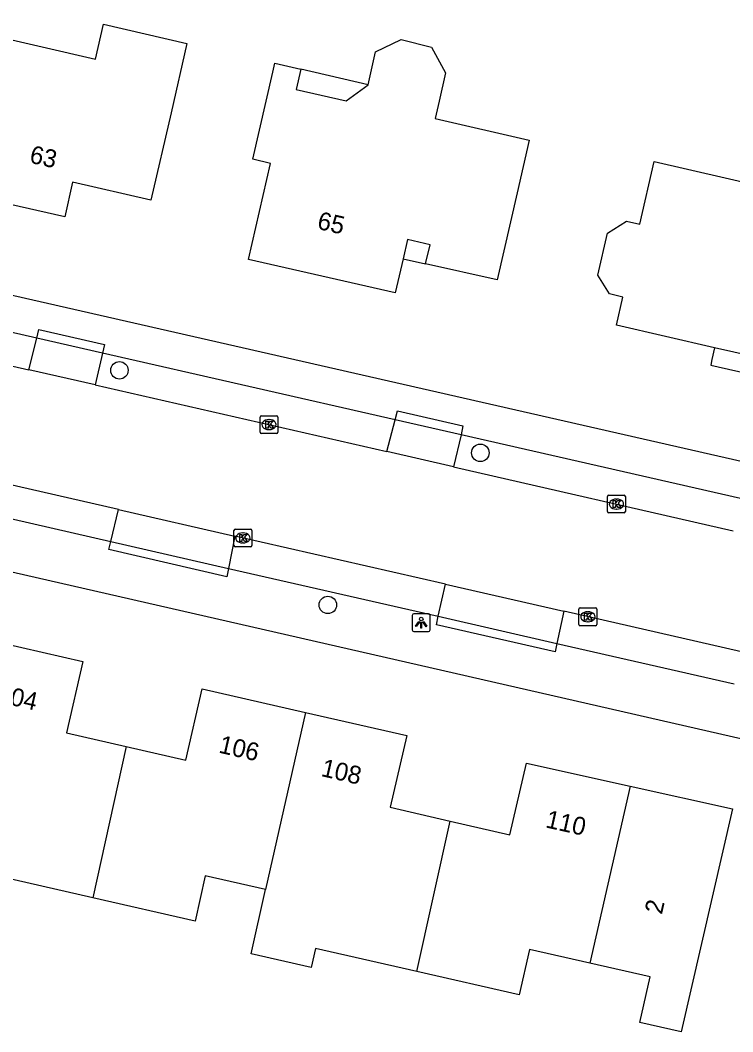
# Model space of a CAD drawing. Extents: x 159628 to 160723, y 388176 to 389416.
# Drawn here: x 160277.9 to 160317.8, y 388682.2 to 388738.8 of the extents above; entities that cross this region are included whole.
import ezdxf

# ---------------------------------------------------------------- set-up
doc = ezdxf.new("R2010")
doc.units = 0
for name, color, linetype in [('IMGEO_Boom', 7, 'Continuous'), ('IMGEO_Kolk', 7, 'Continuous'), ('IMGEO_Lichtpunt', 7, 'Continuous'), ('IMGEO_Pand', 7, 'Continuous'), ('IMGEO_Pand_nummerreeks', 7, 'Continuous'), ('IMGEO_Pand_overbouw', 7, 'Continuous'), ('IMGEO_Parkeervlak_open', 7, 'Continuous'), ('IMGEO_Rijbaan_lokaal_gesloten', 7, 'Continuous'), ('IMGEO_Voetpad_open', 7, 'Continuous')]:
    doc.layers.add(name, color=color, linetype=linetype)

msp = doc.modelspace()

# ---------------------------------------------------------------- linework, layer by layer
at = {"layer": 'IMGEO_Boom'}
for centre in [(160283.483, 388719.176), (160303.688, 388714.56), (160295.153, 388706.051)]:
    msp.add_circle(centre, 0.489, dxfattribs=at)
at = {"layer": 'IMGEO_Kolk'}
for p, q in [((160291.358, 388715.712), (160291.358, 388716.564)), ((160291.433, 388716.638), (160292.285, 388716.638)), ((160291.846, 388716.418), (160291.871, 388716.418)), ((160292.359, 388716.564), (160292.359, 388715.712)), ((160291.869, 388715.858), (160291.844, 388715.858)), ((160292.285, 388715.638), (160291.433, 388715.638)), ((160310.81, 388711.268), (160310.81, 388712.12)), ((160310.885, 388712.194), (160311.737, 388712.194)), ((160311.298, 388711.974), (160311.323, 388711.974)), ((160311.811, 388712.12), (160311.811, 388711.268)), ((160311.321, 388711.414), (160311.296, 388711.414)), ((160311.737, 388711.194), (160310.885, 388711.194)), ((160289.895, 388709.37), (160289.895, 388710.222)), ((160289.97, 388710.296), (160290.822, 388710.296)), ((160290.383, 388710.076), (160290.408, 388710.076)), ((160290.896, 388710.222), (160290.896, 388709.37)), ((160290.406, 388709.516), (160290.381, 388709.516)), ((160290.822, 388709.296), (160289.97, 388709.296)), ((160309.209, 388704.964), (160309.209, 388705.816)), ((160309.284, 388705.89), (160310.136, 388705.89)), ((160309.697, 388705.67), (160309.722, 388705.67)), ((160310.21, 388705.816), (160310.21, 388704.964)), ((160309.72, 388705.11), (160309.695, 388705.11)), ((160310.136, 388704.89), (160309.284, 388704.89))]:
    msp.add_line(p, q, dxfattribs=at)
for points in [[(160291.358, 388715.712), (160291.358, 388716.564)], [(160291.433, 388716.638), (160292.285, 388716.638)], [(160291.679, 388716.338), (160291.802, 388716.338), (160291.802, 388716.187), (160291.932, 388716.338), (160292.096, 388716.338), (160291.95, 388716.187), (160292.103, 388715.938), (160291.951, 388715.938), (160291.866, 388716.102), (160291.802, 388716.035), (160291.802, 388715.938), (160291.679, 388715.938), (160291.679, 388716.338)], [(160292.359, 388716.564), (160292.359, 388715.712)], [(160292.285, 388715.638), (160291.433, 388715.638)], [(160310.81, 388711.268), (160310.81, 388712.12)], [(160310.885, 388712.194), (160311.737, 388712.194)], [(160311.131, 388711.894), (160311.254, 388711.894), (160311.254, 388711.743), (160311.384, 388711.894), (160311.548, 388711.894), (160311.402, 388711.743), (160311.555, 388711.494), (160311.403, 388711.494), (160311.318, 388711.658), (160311.254, 388711.591), (160311.254, 388711.494), (160311.131, 388711.494), (160311.131, 388711.894)], [(160311.811, 388712.12), (160311.811, 388711.268)], [(160311.737, 388711.194), (160310.885, 388711.194)], [(160289.895, 388709.37), (160289.895, 388710.222)], [(160289.97, 388710.296), (160290.822, 388710.296)], [(160290.896, 388710.222), (160290.896, 388709.37)], [(160290.216, 388709.996), (160290.339, 388709.996), (160290.339, 388709.845), (160290.469, 388709.996), (160290.633, 388709.996), (160290.487, 388709.845), (160290.64, 388709.596), (160290.488, 388709.596), (160290.403, 388709.76), (160290.339, 388709.693), (160290.339, 388709.596), (160290.216, 388709.596), (160290.216, 388709.996)], [(160290.822, 388709.296), (160289.97, 388709.296)], [(160309.209, 388704.964), (160309.209, 388705.816)], [(160309.284, 388705.89), (160310.136, 388705.89)], [(160309.53, 388705.59), (160309.653, 388705.59), (160309.653, 388705.439), (160309.783, 388705.59), (160309.947, 388705.59), (160309.801, 388705.439), (160309.954, 388705.19), (160309.802, 388705.19), (160309.717, 388705.354), (160309.653, 388705.287), (160309.653, 388705.19), (160309.53, 388705.19), (160309.53, 388705.59)], [(160310.21, 388705.816), (160310.21, 388704.964)], [(160310.136, 388704.89), (160309.284, 388704.89)]]:
    msp.add_lwpolyline(points, dxfattribs=at)
for centre, start, end in [((160291.435, 388716.562), 91.552, 178.448), ((160291.435, 388716.562), 91.552, 178.448), ((160292.283, 388716.562), 1.552, 88.448), ((160292.283, 388716.562), 1.552, 88.448), ((160291.435, 388715.714), 181.552, 268.448), ((160291.435, 388715.714), 181.552, 268.448), ((160292.283, 388715.714), 271.552, 358.448), ((160292.283, 388715.714), 271.552, 358.448), ((160310.887, 388712.118), 91.552, 178.448), ((160310.887, 388712.118), 91.552, 178.448), ((160311.735, 388712.118), 1.552, 88.448), ((160311.735, 388712.118), 1.552, 88.448), ((160310.887, 388711.27), 181.552, 268.448), ((160310.887, 388711.27), 181.552, 268.448), ((160311.735, 388711.27), 271.552, 358.448), ((160311.735, 388711.27), 271.552, 358.448), ((160289.972, 388710.22), 91.552, 178.448), ((160289.972, 388710.22), 91.552, 178.448), ((160290.82, 388710.22), 1.552, 88.448), ((160290.82, 388710.22), 1.552, 88.448), ((160289.972, 388709.372), 181.552, 268.448), ((160289.972, 388709.372), 181.552, 268.448), ((160290.82, 388709.372), 271.552, 358.448), ((160290.82, 388709.372), 271.552, 358.448), ((160309.286, 388705.814), 91.552, 178.448), ((160309.286, 388705.814), 91.552, 178.448), ((160310.134, 388705.814), 1.552, 88.448), ((160310.134, 388705.814), 1.552, 88.448), ((160309.286, 388704.966), 181.552, 268.448), ((160309.286, 388704.966), 181.552, 268.448), ((160310.134, 388704.966), 271.552, 358.448), ((160310.134, 388704.966), 271.552, 358.448)]:
    msp.add_arc(centre, 0.0765, start, end, dxfattribs=at)
for centre, major_axis, ratio, start_param, end_param in [((160291.845, 388716.138), (-0.387, 0.002), 0.722429, 4.712389, 7.853982), ((160291.87, 388716.138), (-0.39, 0.002), 0.717154, 1.570796, 4.712389), ((160311.297, 388711.694), (-0.387, 0.002), 0.722429, 4.712389, 7.853982), ((160311.322, 388711.694), (-0.39, 0.002), 0.717154, 1.570796, 4.712389), ((160290.382, 388709.796), (-0.387, 0.002), 0.722429, 4.712389, 7.853982), ((160290.407, 388709.796), (-0.39, 0.002), 0.717154, 1.570796, 4.712389), ((160309.696, 388705.39), (-0.387, 0.002), 0.722429, 4.712389, 7.853982), ((160309.721, 388705.39), (-0.39, 0.002), 0.717154, 1.570796, 4.712389)]:
    msp.add_ellipse(centre, major_axis=major_axis, ratio=ratio, start_param=start_param, end_param=end_param, dxfattribs=at)
at = {"layer": 'IMGEO_Lichtpunt'}
for p, q in [((160300.783, 388705.556), (160299.975, 388705.556)), ((160300.783, 388705.556), (160299.975, 388705.556)), ((160299.881, 388705.461), (160299.881, 388704.654)), ((160299.881, 388705.461), (160299.881, 388704.654)), ((160300.877, 388704.654), (160300.877, 388705.461)), ((160300.877, 388704.654), (160300.877, 388705.461)), ((160299.975, 388704.56), (160300.783, 388704.56)), ((160299.975, 388704.56), (160300.783, 388704.56))]:
    msp.add_line(p, q, dxfattribs=at)
for points in [[(160300.255, 388705.125), (160300.294, 388705.097), (160300.106, 388704.835), (160300.068, 388704.862), (160300.255, 388705.125)], [(160300.357, 388705.077), (160300.404, 388705.077), (160300.404, 388704.755), (160300.357, 388704.755), (160300.357, 388705.077)], [(160300.467, 388705.097), (160300.505, 388705.124), (160300.692, 388704.862), (160300.653, 388704.834), (160300.467, 388705.097)]]:
    msp.add_lwpolyline(points, dxfattribs=at)
msp.add_circle((160300.38, 388705.259), 0.0994, dxfattribs=at)
for centre, start, end in [((160299.975, 388705.461), 90, 180), ((160299.975, 388705.461), 90, 180), ((160300.783, 388705.461), 0, 90), ((160300.783, 388705.461), 0, 90), ((160299.975, 388704.654), 180, 270), ((160299.975, 388704.654), 180, 270), ((160300.783, 388704.654), 270, 0), ((160300.783, 388704.654), 270, 360)]:
    msp.add_arc(centre, 0.0946, start, end, dxfattribs=at)
at = {"layer": 'IMGEO_Pand'}
for points in [[(160285.249, 388728.7), (160280.851, 388729.708), (160280.422, 388727.763), (160276.879, 388728.561), (160277.08, 388729.553), (160275.229, 388729.974), (160270.881, 388730.962), (160272.002, 388735.835), (160272.676, 388738.762), (160282.135, 388736.585), (160282.584, 388738.535), (160287.265, 388737.458), (160286.371, 388733.573), (160285.249, 388728.7)], [(160300.963, 388737.26), (160301.742, 388735.812), (160301.379, 388734.236), (160301.154, 388733.259), (160306.429, 388732.045), (160305.752, 388729.103), (160304.63, 388724.23), (160300.624, 388725.14), (160300.878, 388726.188), (160299.614, 388726.494), (160299.368, 388725.42), (160298.928, 388723.504), (160290.7, 388725.378), (160291.937, 388730.753), (160290.95, 388730.98), (160292.072, 388735.853), (160292.187, 388736.352), (160293.634, 388736.019), (160293.374, 388734.891), (160296.171, 388734.247), (160297.405, 388735.151), (160297.828, 388736.989), (160299.26, 388737.686), (160300.963, 388737.26)], [(160313.422, 388730.854), (160321.608, 388728.971), (160326.48, 388727.85), (160324.326, 388718.718), (160323.62, 388718.872), (160323.369, 388717.93), (160318.735, 388718.982), (160318.96, 388719.942), (160316.808, 388720.435), (160311.313, 388721.693), (160311.677, 388723.273), (160310.927, 388723.446), (160310.266, 388724.501), (160310.804, 388726.841), (160311.864, 388727.519), (160312.614, 388727.346), (160313.422, 388730.854)], [(160275.731, 388704.194), (160281.44, 388702.89), (160280.524, 388698.892), (160283.863, 388698.127)], [(160283.863, 388698.127), (160287.204, 388697.362), (160288.12, 388701.36), (160293.901, 388700.037)], [(160293.901, 388700.037), (160291.663, 388690.136)], [(160293.901, 388700.037), (160299.57, 388698.74), (160298.648, 388694.73), (160301.997, 388693.96)], [(160283.863, 388698.127), (160281.989, 388689.665)], [(160301.997, 388693.96), (160305.348, 388693.19), (160306.27, 388697.2), (160312.07, 388695.912)], [(160312.07, 388695.912), (160317.8, 388694.64), (160314.94, 388682.17), (160312.62, 388682.696), (160313.198, 388685.237), (160309.822, 388686.005)], [(160312.07, 388695.912), (160309.822, 388686.005)], [(160281.989, 388689.665), (160276.272, 388690.966), (160276.85, 388693.506), (160273.483, 388694.272)], [(160300.139, 388685.536), (160301.997, 388693.96)], [(160291.663, 388690.136), (160288.292, 388690.903), (160287.714, 388688.363), (160281.989, 388689.665)], [(160300.139, 388685.536), (160294.456, 388686.829), (160294.216, 388685.773), (160290.85, 388686.539), (160291.663, 388690.136)], [(160309.822, 388686.005), (160306.446, 388686.773), (160305.869, 388684.232), (160300.139, 388685.536)]]:
    msp.add_lwpolyline(points, dxfattribs=at)
at = {"layer": 'IMGEO_Pand_overbouw'}
for points in [[(160297.405, 388735.151), (160293.634, 388736.019), (160293.374, 388734.891), (160296.171, 388734.247)], [(160299.368, 388725.42), (160300.624, 388725.14), (160300.878, 388726.188), (160299.614, 388726.494)], [(160316.808, 388720.435), (160316.656, 388719.785), (160316.587, 388719.467), (160317.001, 388719.377), (160318.735, 388718.982), (160318.96, 388719.942)]]:
    msp.add_lwpolyline(points, close=True, dxfattribs=at)
at = {"layer": 'IMGEO_Parkeervlak_open'}
for points in [[(160278.409, 388719.21), (160278.853, 388720.976)], [(160282.542, 388720.135), (160282.132, 388718.359)], [(160298.451, 388714.631), (160298.916, 388716.405)], [(160302.608, 388715.563), (160302.187, 388713.777)], [(160282.993, 388709.603), (160283.422, 388711.389)], [(160289.945, 388709.9), (160289.592, 388708.096)], [(160301.333, 388705.414), (160301.742, 388707.207)], [(160308.359, 388705.697), (160307.972, 388703.897)]]:
    msp.add_lwpolyline(points, dxfattribs=at)
at = {"layer": 'IMGEO_Rijbaan_lokaal_gesloten'}
for points in [[(160265.053, 388722.262), (160278.409, 388719.21)], [(160282.132, 388718.359), (160278.409, 388719.21)], [(160282.132, 388718.359), (160298.451, 388714.631)], [(160302.187, 388713.777), (160298.451, 388714.631)], [(160283.422, 388711.389), (160272.231, 388713.943)], [(160302.187, 388713.777), (160317.848, 388710.198)], [(160283.422, 388711.389), (160289.945, 388709.9)], [(160301.742, 388707.207), (160289.945, 388709.9)], [(160301.742, 388707.207), (160308.359, 388705.697)], [(160321.161, 388702.775), (160308.359, 388705.697)]]:
    msp.add_lwpolyline(points, dxfattribs=at)
at = {"layer": 'IMGEO_Voetpad_open'}
for points in [[(160246.042, 388730.589), (160248.219, 388730.046), (160325.998, 388712.335)], [(160278.853, 388720.976), (160265.457, 388724.028)], [(160278.853, 388720.976), (160278.979, 388721.468), (160282.656, 388720.627), (160282.542, 388720.135)], [(160282.542, 388720.135), (160278.853, 388720.976)], [(160298.916, 388716.405), (160282.542, 388720.135)], [(160321.781, 388697.748), (160237.27, 388717.058), (160229.749, 388718.77)], [(160298.916, 388716.405), (160299.053, 388716.914), (160302.706, 388716.071), (160302.608, 388715.563)], [(160302.608, 388715.563), (160298.916, 388716.405)], [(160318.255, 388711.998), (160302.608, 388715.563)], [(160271.843, 388712.15), (160282.993, 388709.603)], [(160289.592, 388708.096), (160289.502, 388707.619), (160282.881, 388709.142), (160282.993, 388709.603)], [(160282.993, 388709.603), (160289.592, 388708.096)], [(160289.592, 388708.096), (160301.333, 388705.414)], [(160307.972, 388703.897), (160307.871, 388703.42), (160301.244, 388704.929), (160301.333, 388705.414)], [(160301.333, 388705.414), (160307.972, 388703.897)], [(160307.972, 388703.897), (160317.901, 388701.629)]]:
    msp.add_lwpolyline(points, dxfattribs=at)

# ---------------------------------------------------------------- texts
at = {"layer": 'IMGEO_Pand_nummerreeks'}
for s, rotation, p in [('63', 347.3069, (160278.399, 388730.801)), ('65', 347.1829, (160294.508, 388727.101)), ('104', 347.1331, (160276.587, 388700.634)), ('106', 347.1114, (160288.996, 388697.795)), ('108', 347.1142, (160294.725, 388696.484)), ('110', 347.4817, (160307.294, 388693.612)), ('2', 77.0826, (160313.851, 388688.698))]:
    msp.add_text(s, height=1, rotation=rotation, dxfattribs=at).set_placement(p)

doc.saveas('drawing.dxf')
